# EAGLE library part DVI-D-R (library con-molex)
CONNECTOR MiroCross(TM)-DVI i/0 plug and receptacle connector system (scart)
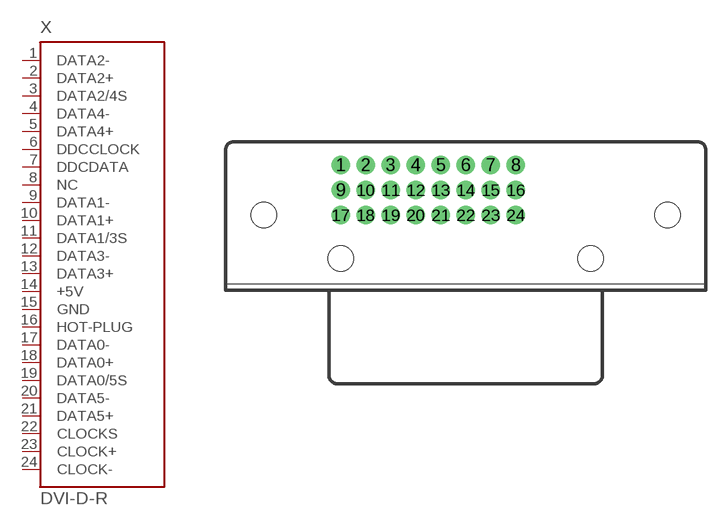
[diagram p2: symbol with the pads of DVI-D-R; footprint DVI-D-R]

Designator prefix X

## DVI-D-R (OC_FARNELL: unknown; OC_NEWARK: unknown)  [DVI-D-R]
1  DATA2-  pas
2  DATA2+  pas
3  DATA2/4S  pas
4  DATA4-  pas
5  DATA4+  pas
6  DDCCLOCK  pas
7  DDCDATA  pas
8  NC  pas
9  DATA1-  pas
10  DATA1+  pas
11  DATA1/3S  pas
12  DATA3-  pas
13  DATA3+  pas
14  +5V  pwr
15  GND  pwr
16  HOT-PLUG  pas
17  DATA0-  pas
18  DATA0+  pas
19  DATA0/5S  pas
20  DATA5-  pas
21  DATA5+  pas
22  CLOCKS  pas
23  CLOCK+  pas
24  CLOCK-  pas

## Footprint DVI-D-R (pad centres in mm)
CONNECTOR MiroCross(TM)-DVI i/0 plug and receptacle connector system (scart)
drill 0.864 pad 1.397 round: 1 -9.525,6.985; 2 -7.62,6.985; 3 -5.715,6.985; 4 -3.81,6.985; 5 -1.905,6.985; 6 0,6.985; 7 1.905,6.985; 8 3.81,6.985; 9 -9.525,5.08; 10 -7.62,5.08; 11 -5.715,5.08; 12 -3.81,5.08; 13 -1.905,5.08; 14 0,5.08; 15 1.905,5.08; 16 3.81,5.08; 17 -9.525,3.175; 18 -7.62,3.175; 19 -5.715,3.175; 20 -3.81,3.175; 21 -1.905,3.175; 22 0,3.175; 23 1.905,3.175; 24 3.81,3.175
hole 1.93 at -15.367,3.175
hole 1.93 at 15.367,3.175
hole 1.93 at -9.525,-0.127
hole 1.93 at 9.525,-0.127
